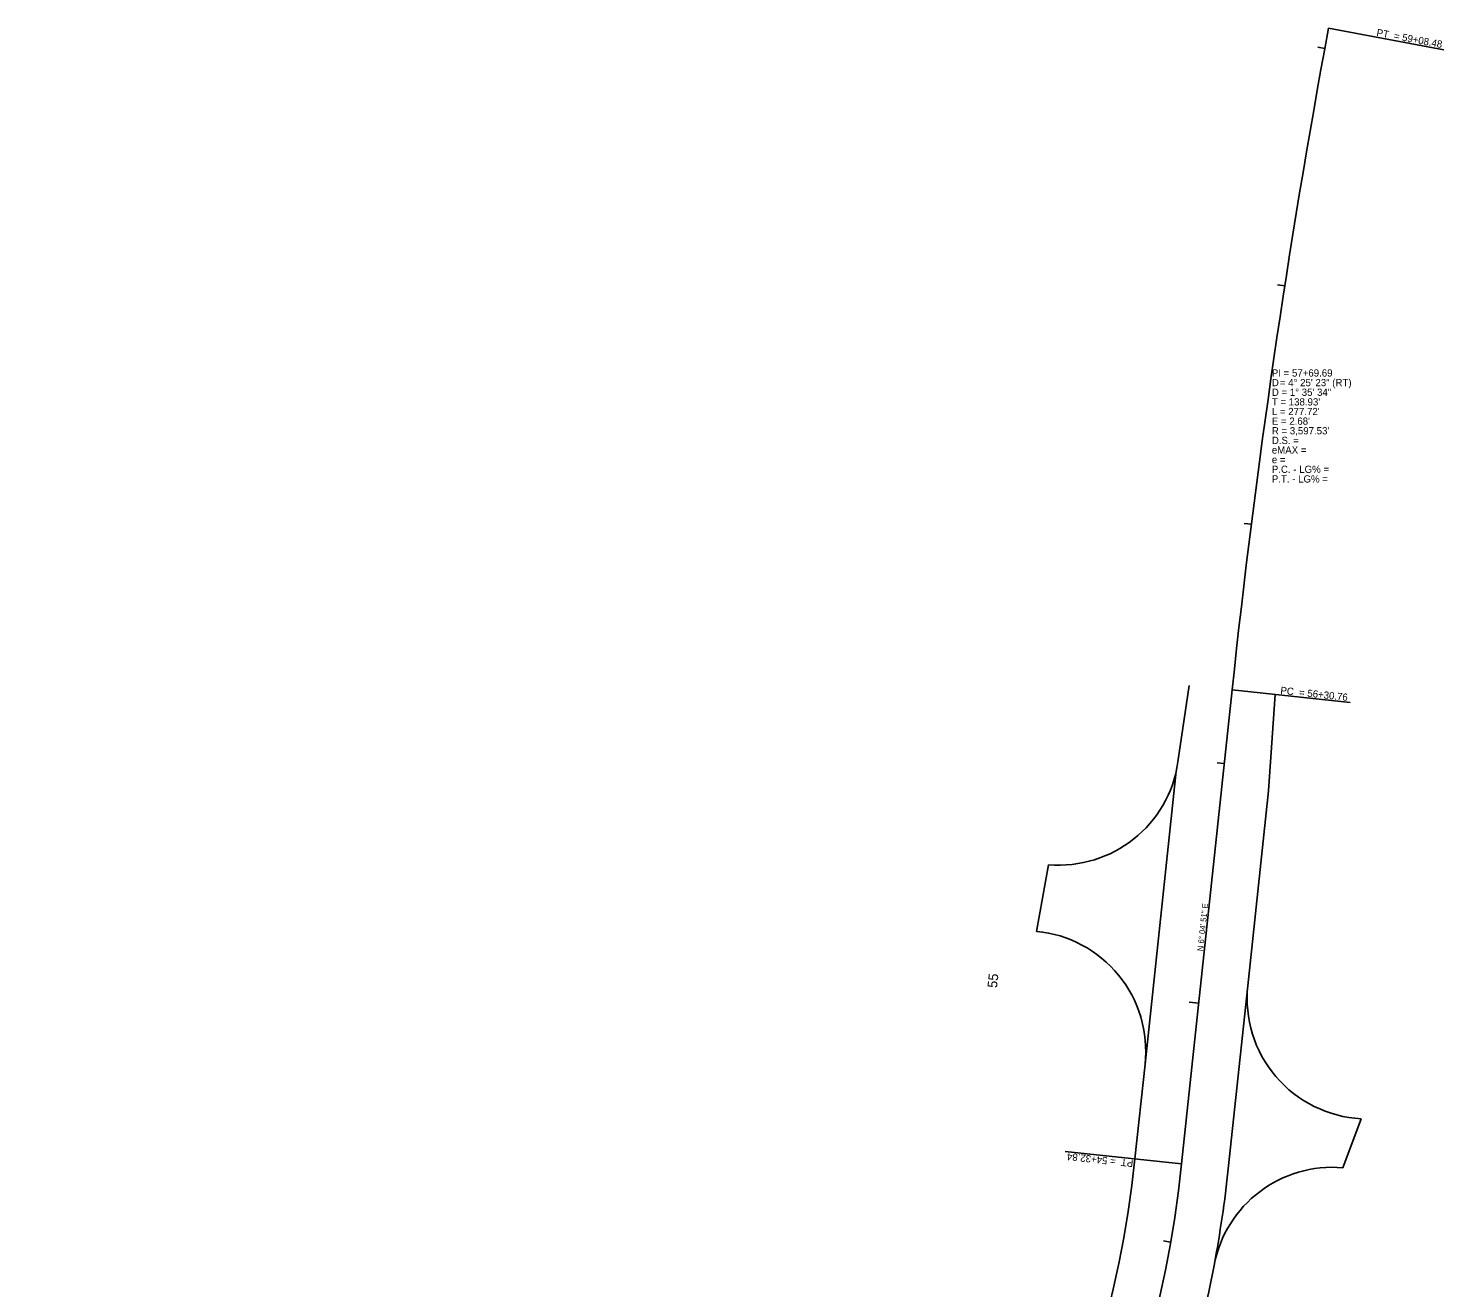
# Model space of a CAD drawing. Extents: x 2004390 to 2007638, y 1136392 to 1138193.
# Drawn here: x 2007050 to 2007638, y 1137670 to 1138193 of the extents above; entities that cross this region are included whole.
import ezdxf

# ---------------------------------------------------------------- set-up
doc = ezdxf.new("R2010")
doc.units = 0
for name, color, linetype in [('RD_HC_Cl', 7, 'Continuous'), ('RD_HC_Data', 7, 'Continuous'), ('RD_HC_Data_Tic', 7, 'Continuous'), ('RD_HC_TX_Sta20', 7, 'Continuous'), ('RD_PD_Final_TrvlWay', 7, 'Continuous')]:
    doc.layers.add(name, color=color, linetype=linetype)

msp = doc.modelspace()

# ---------------------------------------------------------------- linework, layer by layer
at = {"layer": 'RD_HC_Cl'}
msp.add_line((2007529.52, 1137721.07), (2007550.49, 1137917.88), dxfattribs=at)
for centre, radius, start, end in [((2011127.78, 1137536.78), 3597.53, 169.496, 173.91904), ((2007047.25, 1137772.45), 485, 272.45467, 353.91904)]:
    msp.add_arc(centre, radius, start, end, dxfattribs=at)
at = {"layer": 'RD_HC_Data'}
for p, q in [((2007590.53, 1138192.62), (2007638.38, 1138183.75)), ((2007550.49, 1137917.88), (2007599.49, 1137912.66)), ((2007529.52, 1137721.07), (2007481.16, 1137726.23))]:
    msp.add_line(p, q, dxfattribs=at)
at = {"layer": 'RD_HC_Data_Tic'}
for p, q in [((2007589, 1138184.29), (2007586.05, 1138184.83)), ((2007572.37, 1138085.68), (2007569.4, 1138086.14)), ((2007558.49, 1137986.65), (2007555.51, 1137987.03)), ((2007547.23, 1137887.29), (2007544.25, 1137887.61)), ((2007536.64, 1137787.85), (2007532.66, 1137788.28)), ((2007524.94, 1137688.56), (2007521.99, 1137689.08))]:
    msp.add_line(p, q, dxfattribs=at)
at = {"layer": 'RD_PD_Final_TrvlWay'}
for p, q in [((2007527.99, 1137887.97), (2007532.59, 1137919.78)), ((2007565.64, 1137876.04), (2007568.39, 1137915.97)), ((2007527.29, 1137884.16), (2007514.33, 1137762.52)), ((2007557.01, 1137795.04), (2007565.64, 1137876.04)), ((2007469.29, 1137817.6), (2007474.27, 1137845.3)), ((2007557.01, 1137795.04), (2007548.91, 1137719.01)), ((2007514.33, 1137762.52), (2007510.13, 1137723.14)), ((2007596.5, 1137719.46), (2007604.1, 1137739.81))]:
    msp.add_line(p, q, dxfattribs=at)
for centre, radius, start, end in [((2007478.51, 1137895.13), 50, 265.1461, 351.77145), ((2007464.61, 1137767.82), 50, 353.91904, 84.6269), ((2007606.73, 1137789.74), 50, 173.91904, 266.97721), ((2007047.25, 1137772.45), 465.5, 270.39285, 353.91904), ((2007592.14, 1137669.65), 50, 84.9978, 169.31642), ((2007047.25, 1137772.45), 504.5, 349.31642, 353.91904), ((2007047.25, 1137772.45), 504.5, 270.8238, 349.31642)]:
    msp.add_arc(centre, radius, start, end, dxfattribs=at)

# ---------------------------------------------------------------- texts
at = {"layer": 'RD_HC_Data'}
for s, height, rotation, p in [('PT  = 59+08.48', 3, 349.496, (2007610.29, 1138189.47)), ('PC  = 56+30.76', 3, 353.91904, (2007570.43, 1137916.26)), ('N 6%%d 04\' 51" E', 2.4, 83.91904, (2007538.42, 1137809.28)), ('PT  = 54+32.84', 3, 173.91904, (2007509.58, 1137722.69))]:
    msp.add_text(s, height=height, rotation=rotation, dxfattribs=at).set_placement(p)
for s, p in [('PI = 57+69.69', (2007567, 1138048)), ('D', (2007567, 1138044)), ('   = 4%%d 25\' 23" (RT)', (2007567, 1138044)), ('D = 1%%d 35\' 34"', (2007567, 1138040)), ("T = 138.93'", (2007567, 1138036)), ("L = 277.72'", (2007567, 1138032)), ("E = 2.68'", (2007567, 1138028)), ("R = 3,597.53'", (2007567, 1138024)), ('D.S. = ', (2007567, 1138020)), ('eMAX = ', (2007567, 1138016)), ('e = ', (2007567, 1138012)), ('P.C. - LG% = ', (2007567, 1138008)), ('P.T. - LG% = ', (2007567, 1138004))]:
    msp.add_text(s, height=3, dxfattribs=at).set_placement(p)
at = {"layer": 'RD_HC_TX_Sta20'}
msp.add_text('55', height=4, rotation=83.91904, dxfattribs=at).set_placement((2007452.81, 1137793.97))

doc.saveas('drawing.dxf')
